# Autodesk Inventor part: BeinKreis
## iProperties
Author: Standard
Created: 2002-11
Part Number: BeinKreis
Material: Standard
Document SubType Name: Modellieren
Designer: Standard
Control State: 0
Master: False
Checked Out: False
PropertySet Name: Design Tracking Control
Shininess: 20.0
Angle Display Precision: 2
Document Length Units: 11269
Document Angle Units: 11283
Document Time Units: 11279
Document Mass Units: 11290
Document Length Units Precision: 3
Document Angle Units Precision: 2
Compacted: False
PropertySet Name: _Private Model Information
Density: 0.0
Volumn: 0.0
Area: 0.0
PropertySet Name: Model Information
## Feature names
1. Extrusion1
2. Extrusion2
3. Extrusion3
4. Extrusion4
